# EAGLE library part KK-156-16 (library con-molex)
KK 156 HEADER Source: http://www.molex.com/pdm_docs/sd/026604100_sd.pdf
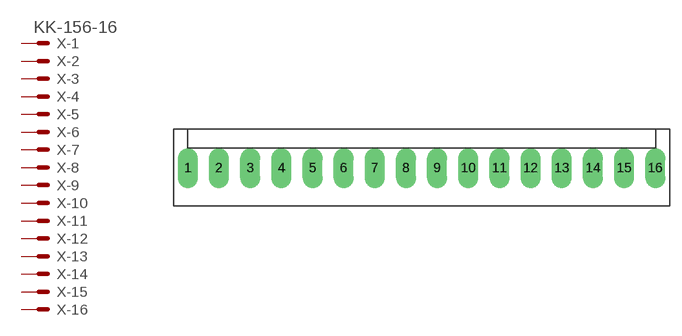
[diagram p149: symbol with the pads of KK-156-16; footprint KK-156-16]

Designator prefix X; gates -1=MV -2=M -3=M -4=M -5=M -6=M -7=M -8=M -9=M -10=M -11=M -12=M -13=M -14=M -15=M -16=M

## KK-156-16 (OC_FARNELL: unknown; OC_NEWARK: unknown)  [KK-156-16]
1  -1:S  pas
2  -2:S  pas
3  -3:S  pas
4  -4:S  pas
5  -5:S  pas
6  -6:S  pas
7  -7:S  pas
8  -8:S  pas
9  -9:S  pas
10  -10:S  pas
11  -11:S  pas
12  -12:S  pas
13  -13:S  pas
14  -14:S  pas
15  -15:S  pas
16  -16:S  pas

## Footprint KK-156-16 (pad centres in mm)
KK 156 HEADER Source: http://www.molex.com/pdm_docs/sd/026604100_sd.pdf
drill 1.7 pad 2.184 long: 1 -29.7,0; 2 -25.74,0; 3 -21.78,0; 4 -17.82,0; 5 -13.86,0; 6 -9.9,0; 7 -5.94,0; 8 -1.98,0; 9 1.98,0; 10 5.94,0; 11 9.9,0; 12 13.86,0; 13 17.82,0; 14 21.78,0; 15 25.74,0; 16 29.7,0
